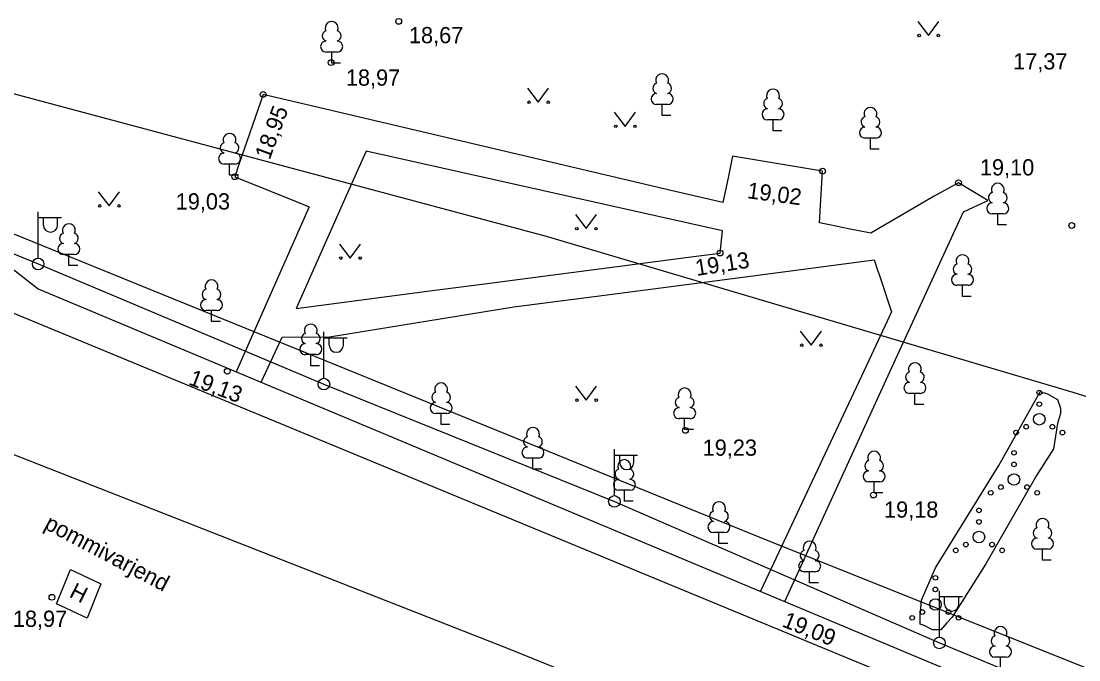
# Model space of a CAD drawing. Extents: x 713497 to 713863, y 6590062 to 6590327.
# Drawn here: x 713708.83 to 713754.44, y 6590250.76 to 6590278.31 of the extents above; entities that cross this region are included whole.
import ezdxf

# ---------------------------------------------------------------- set-up
doc = ezdxf.new("R2010")
doc.units = 0
for name, color, linetype in [('HALJASTUS', 7, 'Continuous'), ('HOONE', 7, 'Continuous'), ('KORGUS', 7, 'Continuous'), ('KPKAABEL', 7, 'Continuous'), ('MPKAABEL', 7, 'Continuous'), ('POST', 7, 'Continuous'), ('PUU', 7, 'Continuous'), ('RAJATIS', 7, 'Continuous'), ('SITRASS', 7, 'Continuous'), ('TEE', 7, 'Continuous'), ('TORU NR', 7, 'Continuous'), ('Слой 1', 7, 'Continuous')]:
    doc.layers.add(name, color=color, linetype=linetype)

msp = doc.modelspace()

# ---------------------------------------------------------------- linework, layer by layer
at = {"layer": 'HALJASTUS'}
for p, q in [((713747.487, 6590278.297), (713747.95, 6590277.69)), ((713747.95, 6590277.69), (713748.396, 6590278.297)), ((713730.667, 6590275.417), (713731.13, 6590274.81)), ((713731.13, 6590274.81), (713731.576, 6590275.417)), ((713734.407, 6590274.377), (713734.87, 6590273.77)), ((713734.87, 6590273.77), (713735.316, 6590274.377)), ((713712.157, 6590270.947), (713712.62, 6590270.34)), ((713712.62, 6590270.34), (713713.066, 6590270.947)), ((713732.727, 6590269.967), (713733.19, 6590269.36)), ((713733.19, 6590269.36), (713733.636, 6590269.967)), ((713722.557, 6590268.697), (713723.02, 6590268.09)), ((713723.02, 6590268.09), (713723.466, 6590268.697)), ((713742.427, 6590264.937), (713742.89, 6590264.33)), ((713742.89, 6590264.33), (713743.336, 6590264.937)), ((713732.737, 6590262.567), (713733.2, 6590261.96)), ((713733.2, 6590261.96), (713733.646, 6590262.567))]:
    msp.add_line(p, q, dxfattribs=at)
msp.add_lwpolyline([(713752.7, 6590262.18), (713752.91, 6590262.29), (713753.09, 6590262.23), (713753.52, 6590261.99), (713753.64, 6590261.62), (713753.64, 6590261.38), (713753.52, 6590260.96), (713753.34, 6590259.87), (713752.61, 6590258.72), (713750.43, 6590254.91), (713748.98, 6590252.61), (713748.74, 6590252.36), (713748.49, 6590252.06), (713748.13, 6590252.06), (713747.77, 6590252.24), (713747.59, 6590252.3), (713747.59, 6590252.67), (713747.65, 6590253.33), (713748.25, 6590254.73), (713750.98, 6590259.14), (713752.79, 6590262.35)], dxfattribs=at)
for centre, radius in [((713747.549, 6590277.69), 0.055), ((713748.378, 6590277.69), 0.055), ((713730.729, 6590274.81), 0.055), ((713731.558, 6590274.81), 0.055), ((713734.469, 6590273.77), 0.055), ((713735.298, 6590273.77), 0.055), ((713712.219, 6590270.34), 0.055), ((713713.048, 6590270.34), 0.055), ((713754.13, 6590269.495), 0.125), ((713732.789, 6590269.36), 0.055), ((713733.618, 6590269.36), 0.055), ((713722.619, 6590268.09), 0.055), ((713723.448, 6590268.09), 0.055), ((713742.489, 6590264.33), 0.055), ((713743.318, 6590264.33), 0.055), ((713752.73, 6590262.29), 0.1), ((713732.799, 6590261.96), 0.055), ((713733.628, 6590261.96), 0.055), ((713752.73, 6590261.79), 0.1), ((713752.73, 6590261.14), 0.25), ((713752.165, 6590260.815), 0.1), ((713753.295, 6590260.815), 0.1), ((713751.73, 6590260.565), 0.1), ((713753.73, 6590260.565), 0.1), ((713751.64, 6590259.69), 0.1), ((713751.64, 6590259.19), 0.1), ((713751.64, 6590258.54), 0.25), ((713751.075, 6590258.215), 0.1), ((713752.205, 6590258.215), 0.1), ((713750.64, 6590257.965), 0.1), ((713752.64, 6590257.965), 0.1), ((713750.13, 6590257.21), 0.1), ((713750.13, 6590256.71), 0.1), ((713750.13, 6590256.06), 0.25), ((713749.13, 6590255.485), 0.1), ((713749.565, 6590255.735), 0.1), ((713750.695, 6590255.735), 0.1), ((713751.13, 6590255.485), 0.1), ((713748.25, 6590254.3), 0.1), ((713748.25, 6590253.8), 0.1), ((713748.25, 6590253.15), 0.25), ((713747.685, 6590252.825), 0.1), ((713748.815, 6590252.825), 0.1), ((713747.25, 6590252.575), 0.1), ((713749.25, 6590252.575), 0.1)]:
    msp.add_circle(centre, radius, dxfattribs=at)
at = {"layer": 'KORGUS'}
for centre in [(713725.11, 6590278.3), (713722.2, 6590276.52), (713719.265, 6590275.148), (713743.386, 6590271.839), (713718.042, 6590271.6), (713749.25, 6590271.34), (713738.968, 6590268.308), (713717.72, 6590263.21), (713737.47, 6590260.66), (713745.58, 6590257.87), (713710.16, 6590253.46)]:
    msp.add_circle(centre, 0.125, dxfattribs=at)
at = {"layer": 'KPKAABEL'}
msp.add_lwpolyline([(713815.88, 6590242.79), (713794.35, 6590249.68), (713754.19, 6590262.29), (713731.48, 6590269.02), (713706.45, 6590275.72)], dxfattribs=at)
at = {"layer": 'MPKAABEL'}
for points in [[(713701.219, 6590274.33), (713701.679, 6590274.524), (713703.015, 6590271.361), (713705.012, 6590272.169), (713706.295, 6590269.173), (713709.564, 6590267.835), (713721.885, 6590262.655), (713734.411, 6590257.594), (713748.424, 6590251.492), (713764.059, 6590245.013), (713776.78, 6590239.5)], [(713738.08, 6590234.05), (713742.4, 6590246.15), (713729.77, 6590251.26), (713699.54, 6590263.131)]]:
    msp.add_lwpolyline(points, dxfattribs=at)
at = {"layer": 'POST'}
for p, q in [((713709.564, 6590268.085), (713709.564, 6590270.085)), ((713709.564, 6590269.835), (713710.564, 6590269.835)), ((713709.791, 6590269.514), (713709.791, 6590269.835)), ((713710.403, 6590269.514), (713710.403, 6590269.835)), ((713721.885, 6590262.905), (713721.885, 6590264.905)), ((713721.885, 6590264.655), (713722.885, 6590264.655)), ((713722.112, 6590264.334), (713722.112, 6590264.655)), ((713722.724, 6590264.334), (713722.724, 6590264.655)), ((713734.411, 6590257.844), (713734.411, 6590259.844)), ((713734.411, 6590259.594), (713735.411, 6590259.594)), ((713734.638, 6590259.273), (713734.638, 6590259.594)), ((713735.25, 6590259.273), (713735.25, 6590259.594)), ((713748.424, 6590251.742), (713748.424, 6590253.742)), ((713748.424, 6590253.492), (713749.424, 6590253.492)), ((713748.651, 6590253.171), (713748.651, 6590253.492)), ((713749.263, 6590253.171), (713749.263, 6590253.492))]:
    msp.add_line(p, q, dxfattribs=at)
for centre in [(713709.564, 6590267.835), (713721.885, 6590262.655), (713734.411, 6590257.594), (713748.424, 6590251.492)]:
    msp.add_circle(centre, 0.25, dxfattribs=at)
for centre in [(713710.097, 6590269.514), (713722.418, 6590264.334), (713734.944, 6590259.273), (713748.957, 6590253.171)]:
    msp.add_arc(centre, 0.306, 180, 0, dxfattribs=at)
at = {"layer": 'PUU'}
for p, q in [((713722.46, 6590276.975), (713721.98, 6590276.975)), ((713722.22, 6590276.5), (713722.22, 6590276.975)), ((713722.6, 6590276.5), (713722.22, 6590276.5)), ((713736.71, 6590274.715), (713736.23, 6590274.715)), ((713736.47, 6590274.24), (713736.47, 6590274.715)), ((713736.85, 6590274.24), (713736.47, 6590274.24)), ((713741.49, 6590274.055), (713741.01, 6590274.055)), ((713741.25, 6590273.58), (713741.25, 6590274.055)), ((713741.63, 6590273.58), (713741.25, 6590273.58)), ((713745.69, 6590273.265), (713745.21, 6590273.265)), ((713745.45, 6590272.79), (713745.45, 6590273.265)), ((713745.83, 6590272.79), (713745.45, 6590272.79)), ((713718.06, 6590272.145), (713717.58, 6590272.145)), ((713717.82, 6590271.67), (713717.82, 6590272.145)), ((713718.2, 6590271.67), (713717.82, 6590271.67)), ((713751.18, 6590269.995), (713750.7, 6590269.995)), ((713750.94, 6590269.52), (713750.94, 6590269.995)), ((713751.32, 6590269.52), (713750.94, 6590269.52)), ((713711.13, 6590268.245), (713710.65, 6590268.245)), ((713710.89, 6590267.77), (713710.89, 6590268.245)), ((713711.27, 6590267.77), (713710.89, 6590267.77)), ((713749.66, 6590266.915), (713749.18, 6590266.915)), ((713749.42, 6590266.44), (713749.42, 6590266.915)), ((713749.8, 6590266.44), (713749.42, 6590266.44)), ((713717.28, 6590265.825), (713716.8, 6590265.825)), ((713717.04, 6590265.35), (713717.04, 6590265.825)), ((713717.42, 6590265.35), (713717.04, 6590265.35)), ((713721.56, 6590263.925), (713721.08, 6590263.925)), ((713721.32, 6590263.45), (713721.32, 6590263.925)), ((713721.7, 6590263.45), (713721.32, 6590263.45)), ((713747.61, 6590262.255), (713747.13, 6590262.255)), ((713747.37, 6590261.78), (713747.37, 6590262.255)), ((713727.18, 6590261.385), (713726.7, 6590261.385)), ((713726.94, 6590260.91), (713726.94, 6590261.385)), ((713747.75, 6590261.78), (713747.37, 6590261.78)), ((713737.68, 6590261.165), (713737.2, 6590261.165)), ((713737.44, 6590260.69), (713737.44, 6590261.165)), ((713727.32, 6590260.91), (713726.94, 6590260.91)), ((713737.82, 6590260.69), (713737.44, 6590260.69)), ((713731.14, 6590259.465), (713730.66, 6590259.465)), ((713730.9, 6590258.99), (713730.9, 6590259.465)), ((713731.28, 6590258.99), (713730.9, 6590258.99)), ((713745.85, 6590258.435), (713745.37, 6590258.435)), ((713745.61, 6590257.96), (713745.61, 6590258.435)), ((713735.08, 6590258.075), (713734.6, 6590258.075)), ((713734.84, 6590257.6), (713734.84, 6590258.075)), ((713745.99, 6590257.96), (713745.61, 6590257.96)), ((713735.22, 6590257.6), (713734.84, 6590257.6)), ((713739.16, 6590256.255), (713738.68, 6590256.255)), ((713738.92, 6590255.78), (713738.92, 6590256.255)), ((713739.3, 6590255.78), (713738.92, 6590255.78)), ((713753.11, 6590255.535), (713752.63, 6590255.535)), ((713752.87, 6590255.06), (713752.87, 6590255.535)), ((713753.25, 6590255.06), (713752.87, 6590255.06)), ((713743.07, 6590254.565), (713742.59, 6590254.565)), ((713742.83, 6590254.09), (713742.83, 6590254.565)), ((713743.21, 6590254.09), (713742.83, 6590254.09)), ((713751.3, 6590250.875), (713750.82, 6590250.875)), ((713751.06, 6590250.4), (713751.06, 6590250.875))]:
    msp.add_line(p, q, dxfattribs=at)
for centre, radius, start, end in [((713722.22, 6590278.02), 0.277, 332.5799, 207.4201), ((713722.05, 6590277.673), 0.233, 109.0217, 253.1415), ((713722.39, 6590277.673), 0.233, 286.8508, 70.9859), ((713721.983, 6590277.212), 0.238, 90.0016, 269.3953), ((713722.457, 6590277.212), 0.238, 270.6047, 89.9984), ((713736.47, 6590275.76), 0.277, 332.5799, 207.4201), ((713736.3, 6590275.413), 0.233, 109.0217, 253.1415), ((713736.64, 6590275.413), 0.233, 286.8508, 70.9859), ((713736.233, 6590274.952), 0.238, 90.0016, 269.3953), ((713736.707, 6590274.952), 0.238, 270.6047, 89.9984), ((713741.25, 6590275.1), 0.277, 332.5799, 207.4201), ((713741.08, 6590274.753), 0.233, 109.0217, 253.1415), ((713741.42, 6590274.753), 0.233, 286.8508, 70.9859), ((713741.013, 6590274.292), 0.238, 90.0016, 269.3953), ((713741.487, 6590274.292), 0.238, 270.6047, 89.9984), ((713745.28, 6590273.963), 0.233, 109.0217, 253.1415), ((713745.45, 6590274.31), 0.277, 332.5799, 207.4201), ((713745.62, 6590273.963), 0.233, 286.8508, 70.9859), ((713745.213, 6590273.502), 0.238, 90.0016, 269.3953), ((713745.687, 6590273.502), 0.238, 270.6047, 89.9984), ((713717.82, 6590273.19), 0.277, 332.5799, 207.4201), ((713717.65, 6590272.843), 0.233, 109.0217, 253.1415), ((713717.99, 6590272.843), 0.233, 286.8508, 70.9859), ((713717.583, 6590272.382), 0.238, 90.0016, 269.3953), ((713718.057, 6590272.382), 0.238, 270.6047, 89.9984), ((713750.94, 6590271.04), 0.277, 332.5799, 207.4201), ((713750.77, 6590270.693), 0.233, 109.0217, 253.1415), ((713751.11, 6590270.693), 0.233, 286.8508, 70.9859), ((713750.703, 6590270.232), 0.238, 90.0016, 269.3953), ((713751.177, 6590270.232), 0.238, 270.6047, 89.9984), ((713710.72, 6590268.943), 0.233, 109.0217, 253.1415), ((713710.89, 6590269.29), 0.277, 332.5799, 207.4201), ((713711.06, 6590268.943), 0.233, 286.8508, 70.9859), ((713710.653, 6590268.482), 0.238, 90.0016, 269.3953), ((713711.127, 6590268.482), 0.238, 270.6047, 89.9984), ((713749.42, 6590267.96), 0.277, 332.5799, 207.4201), ((713749.25, 6590267.613), 0.233, 109.0217, 253.1415), ((713749.59, 6590267.613), 0.233, 286.8508, 70.9859), ((713749.183, 6590267.152), 0.238, 90.0016, 269.3953), ((713749.657, 6590267.152), 0.238, 270.6047, 89.9984), ((713717.04, 6590266.87), 0.277, 332.5799, 207.4201), ((713716.87, 6590266.523), 0.233, 109.0217, 253.1415), ((713717.21, 6590266.523), 0.233, 286.8508, 70.9859), ((713716.803, 6590266.062), 0.238, 90.0016, 269.3953), ((713717.277, 6590266.062), 0.238, 270.6047, 89.9984), ((713721.32, 6590264.97), 0.277, 332.5799, 207.4201), ((713721.15, 6590264.623), 0.233, 109.0217, 253.1415), ((713721.49, 6590264.623), 0.233, 286.8508, 70.9859), ((713721.083, 6590264.162), 0.238, 90.0016, 269.3953), ((713721.557, 6590264.162), 0.238, 270.6047, 89.9984), ((713747.37, 6590263.3), 0.277, 332.5799, 207.4201), ((713747.2, 6590262.953), 0.233, 109.0217, 253.1415), ((713747.54, 6590262.953), 0.233, 286.8508, 70.9859), ((713726.77, 6590262.083), 0.233, 109.0217, 253.1415), ((713726.94, 6590262.43), 0.277, 332.5799, 207.4201), ((713727.11, 6590262.083), 0.233, 286.8508, 70.9859), ((713737.44, 6590262.21), 0.277, 332.5799, 207.4201), ((713747.133, 6590262.492), 0.238, 90.0016, 269.3953), ((713747.607, 6590262.492), 0.238, 270.6047, 89.9984), ((713726.703, 6590261.622), 0.238, 90.0016, 269.3953), ((713727.177, 6590261.622), 0.238, 270.6047, 89.9984), ((713737.27, 6590261.863), 0.233, 109.0217, 253.1415), ((713737.61, 6590261.863), 0.233, 286.8508, 70.9859), ((713737.203, 6590261.402), 0.238, 90.0016, 269.3953), ((713737.677, 6590261.402), 0.238, 270.6047, 89.9984), ((713730.9, 6590260.51), 0.277, 332.5799, 207.4201), ((713730.73, 6590260.163), 0.233, 109.0217, 253.1415), ((713731.07, 6590260.163), 0.233, 286.8508, 70.9859), ((713730.663, 6590259.702), 0.238, 90.0016, 269.3953), ((713731.137, 6590259.702), 0.238, 270.6047, 89.9984), ((713745.61, 6590259.48), 0.277, 332.5799, 207.4201), ((713734.84, 6590259.12), 0.277, 332.5799, 207.4201), ((713745.44, 6590259.133), 0.233, 109.0217, 253.1415), ((713745.78, 6590259.133), 0.233, 286.8508, 70.9859), ((713734.67, 6590258.773), 0.233, 109.0217, 253.1415), ((713735.01, 6590258.773), 0.233, 286.8508, 70.9859), ((713745.373, 6590258.672), 0.238, 90.0016, 269.3953), ((713745.847, 6590258.672), 0.238, 270.6047, 89.9984), ((713734.603, 6590258.312), 0.238, 90.0016, 269.3953), ((713735.077, 6590258.312), 0.238, 270.6047, 89.9984), ((713738.92, 6590257.3), 0.277, 332.5799, 207.4201), ((713738.75, 6590256.953), 0.233, 109.0217, 253.1415), ((713739.09, 6590256.953), 0.233, 286.8508, 70.9859), ((713752.87, 6590256.58), 0.277, 332.5799, 207.4201), ((713738.683, 6590256.492), 0.238, 90.0016, 269.3953), ((713739.157, 6590256.492), 0.238, 270.6047, 89.9984), ((713752.7, 6590256.233), 0.233, 109.0217, 253.1415), ((713753.04, 6590256.233), 0.233, 286.8508, 70.9859), ((713752.633, 6590255.772), 0.238, 90.0016, 269.3953), ((713753.107, 6590255.772), 0.238, 270.6047, 89.9984), ((713742.66, 6590255.263), 0.233, 109.0217, 253.1415), ((713742.83, 6590255.61), 0.277, 332.5799, 207.4201), ((713743, 6590255.263), 0.233, 286.8508, 70.9859), ((713742.593, 6590254.802), 0.238, 90.0016, 269.3953), ((713743.067, 6590254.802), 0.238, 270.6047, 89.9984), ((713751.06, 6590251.92), 0.277, 332.5799, 207.4201), ((713750.823, 6590251.112), 0.238, 90.0016, 269.3953), ((713750.89, 6590251.573), 0.233, 109.0217, 253.1415), ((713751.23, 6590251.573), 0.233, 286.8508, 70.9859), ((713751.297, 6590251.112), 0.238, 270.6047, 89.9984)]:
    msp.add_arc(centre, radius, start, end, dxfattribs=at)
at = {"layer": 'RAJATIS'}
msp.add_lwpolyline([(713710.954, 6590254.654), (713712.27, 6590254.036), (713711.678, 6590252.56), (713710.362, 6590253.178), (713710.954, 6590254.654)], dxfattribs=at)
at = {"layer": 'SITRASS'}
msp.add_lwpolyline([(713863.358, 6590205.976), (713841.44, 6590214.83), (713823.81, 6590222.07), (713798.2, 6590232.48), (713769.43, 6590244.2), (713757.31, 6590249.39), (713740.65, 6590256.05), (713706.71, 6590269.85)], dxfattribs=at)
at = {"layer": 'TEE'}
for points in [[(713741.755, 6590253.278), (713746.281, 6590263.184), (713749.195, 6590269.489), (713749.468, 6590270.08), (713750.508, 6590270.577), (713749.868, 6590270.966), (713749.25, 6590271.34), (713748.202, 6590270.761), (713746.063, 6590269.512), (713745.461, 6590269.16), (713744.499, 6590269.355), (713743.685, 6590269.52), (713743.257, 6590269.607), (713743.386, 6590271.839), (713742.872, 6590271.925), (713742.433, 6590271.998), (713739.505, 6590272.488), (713739.311, 6590271.551), (713739.089, 6590270.48), (713737.033, 6590270.964), (713729.222, 6590272.803), (713720.738, 6590274.801), (713719.441, 6590275.107), (713719.265, 6590275.148), (713718.223, 6590272.124), (713718.042, 6590271.6), (713719.589, 6590270.975), (713720.695, 6590270.529), (713721.247, 6590270.306), (713718.105, 6590263.186)], [(713723.706, 6590272.706), (713722.905, 6590270.902), (713720.694, 6590265.921), (713726.331, 6590266.657), (713728.804, 6590266.98), (713737.937, 6590268.173), (713738.968, 6590268.308), (713739.067, 6590269.271), (713733.536, 6590270.508), (713723.706, 6590272.706)], [(713705.99, 6590269.548), (713709.56, 6590266.765), (713802.48, 6590227.84), (713863.358, 6590202.427)], [(713719.183, 6590262.734), (713720.079, 6590264.675), (713722.12, 6590264.7), (713730.073, 6590265.981), (713733.658, 6590266.449), (713739.838, 6590267.256), (713745.616, 6590268.011), (713745.675, 6590267.835), (713745.747, 6590267.618), (713745.838, 6590267.342), (713746.359, 6590265.776), (713745.389, 6590263.701), (713740.705, 6590253.718), (713740.705, 6590253.718)]]:
    msp.add_lwpolyline(points, dxfattribs=at)
at = {"layer": 'Слой 1'}
msp.add_lwpolyline([(713693, 6590272.12), (713754.18, 6590246.82), (713731.07, 6590198.34), (713671.75, 6590227.66)], close=True, dxfattribs=at)

# ---------------------------------------------------------------- texts
at = {"layer": 'HOONE'}
msp.add_text('H', height=0.7, rotation=333.1075, dxfattribs=at).set_placement((713710.864, 6590253.495))
at = {"layer": 'KORGUS'}
for s, p in [('18,67', (713725.553, 6590277.355)), ('17,37', (713751.603, 6590276.225)), ('18,97', (713722.833, 6590275.525)), ('19,10', (713750.171, 6590271.655)), ('19,03', (713715.496, 6590270.185)), ('19,23', (713738.216, 6590259.565)), ('19,18', (713746.036, 6590256.895)), ('18,97', (713708.473, 6590252.185))]:
    msp.add_text(s, height=0.7, dxfattribs=at).set_placement(p)
for s, rotation, p in [('18,95', 69.5635, (713719.544, 6590272.299)), ('19,02', 352.4041, (713740.109, 6590270.675)), ('19,13', 9.0289, (713737.957, 6590267.315)), ('19,13', 339.5058, (713716.01, 6590262.649)), ('19,09', 338.0716, (713741.602, 6590252.215))]:
    msp.add_text(s, height=0.7, rotation=rotation, dxfattribs=at).set_placement(p)
at = {"layer": 'TORU NR'}
msp.add_text('pommivarjend', height=0.7, rotation=332.0924, dxfattribs=at).set_placement((713709.781, 6590256.441))

doc.saveas('drawing.dxf')
